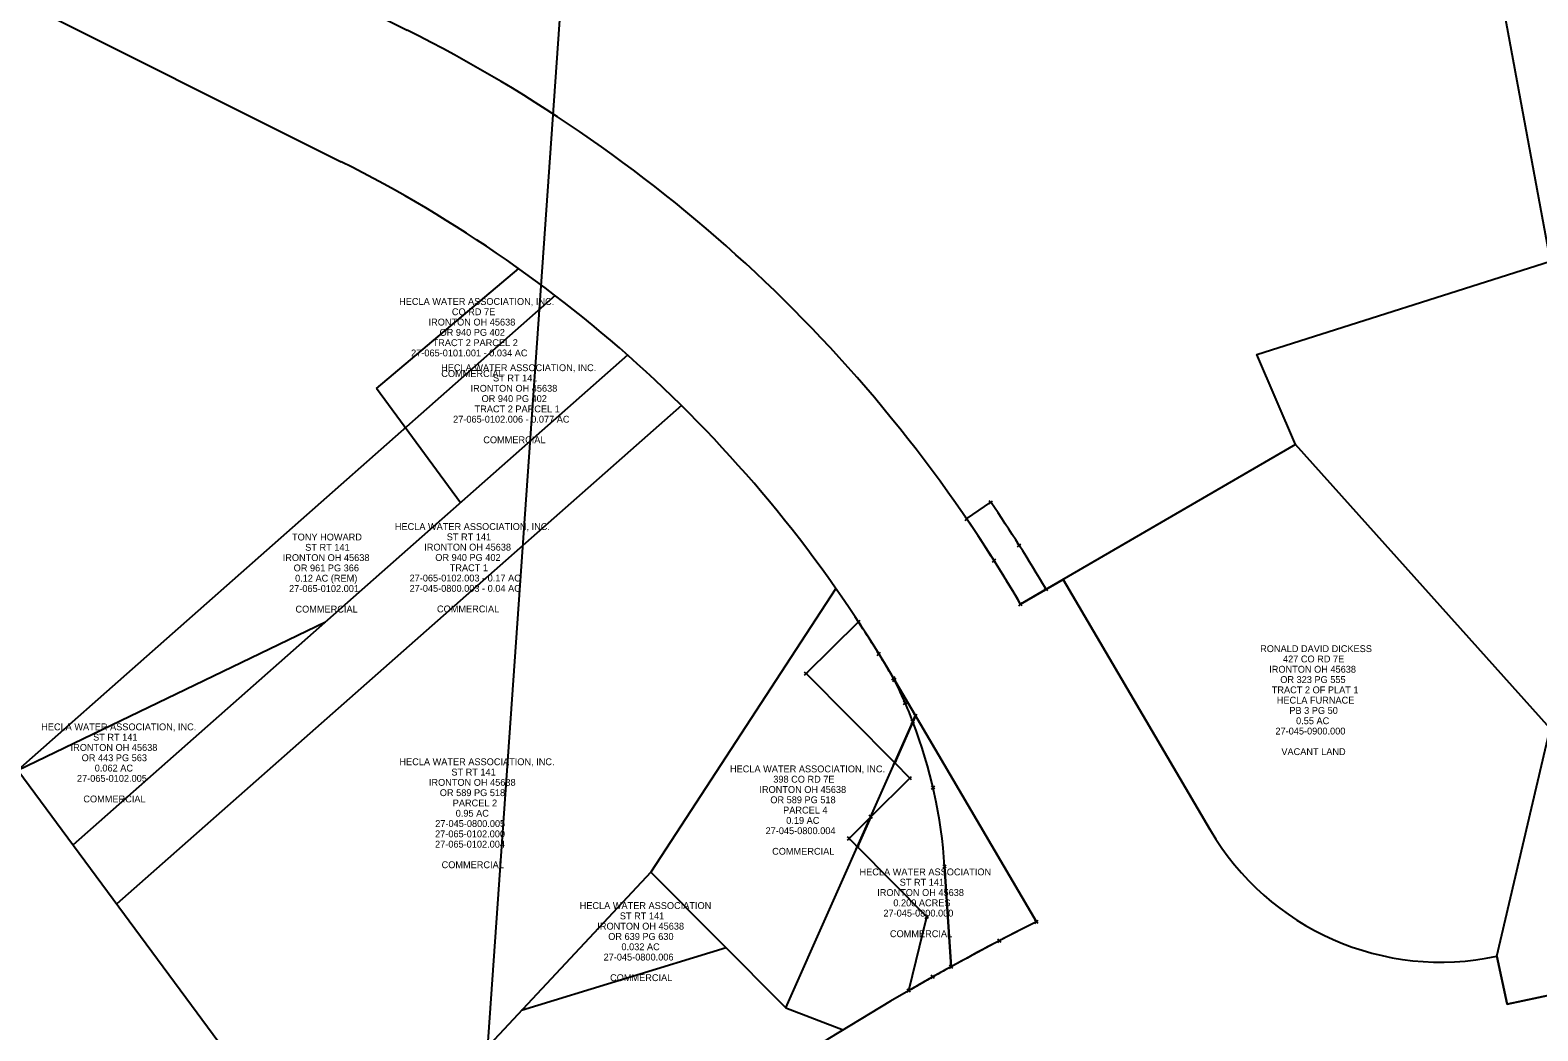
# Model space of a CAD drawing. Extents: x 1926695 to 1928303, y 198652 to 200926.
# Drawn here: x 1927197 to 1927812, y 199742 to 200150 of the extents above; entities that cross this region are included whole.
import ezdxf

# ---------------------------------------------------------------- set-up
doc = ezdxf.new("R2010")
doc.units = 0
for name, color, linetype in [('_CIVIL_CONSTRUCTION', 7, 'Continuous'), ('DR_Ditch', 7, 'Continuous'), ('DR_P_Dike', 7, 'Continuous'), ('DR_P_Storm_Sewer', 7, 'Continuous'), ('PV_P_EOP', 7, 'Continuous'), ('PV_P_Saw_Cut_Line', 7, 'Continuous'), ('RD_P_Cells', 7, 'Continuous'), ('SC_Scratch1', 7, 'Continuous')]:
    doc.layers.add(name, color=color, linetype=linetype)

msp = doc.modelspace()

# ---------------------------------------------------------------- linework, layer by layer
at = {"layer": '_CIVIL_CONSTRUCTION'}
msp.add_line((1927376.1, 199627.83), (1927467.32, 200926.12), dxfattribs=at)
at = {"layer": 'DR_Ditch'}
for p, q in [((1927589.52, 199956.71), (1927588.18, 199958.04)), ((1927588.18, 199956.71), (1927589.52, 199958.04)), ((1927579.61, 199949.95), (1927578.27, 199951.28)), ((1927578.27, 199949.95), (1927579.61, 199951.28)), ((1927601.06, 199939.16), (1927599.72, 199940.5)), ((1927599.72, 199939.16), (1927601.06, 199940.5)), ((1927590.79, 199932.95), (1927589.46, 199934.28)), ((1927589.46, 199932.95), (1927590.79, 199934.28)), ((1927611.99, 199921.24), (1927610.65, 199922.57)), ((1927610.65, 199921.24), (1927611.99, 199922.57)), ((1927601.61, 199915.21), (1927600.27, 199916.55)), ((1927600.27, 199915.21), (1927601.61, 199916.55)), ((1927535.49, 199907.99), (1927534.16, 199909.32)), ((1927534.16, 199907.99), (1927535.49, 199909.32)), ((1927543.79, 199894.93), (1927542.46, 199896.27)), ((1927542.46, 199894.93), (1927543.79, 199896.27)), ((1927514.21, 199886.85), (1927512.87, 199888.18)), ((1927512.87, 199886.85), (1927514.21, 199888.18)), ((1927549.79, 199884.97), (1927548.45, 199886.31)), ((1927548.45, 199884.97), (1927549.79, 199886.31)), ((1927550.15, 199884.36), (1927548.81, 199885.69)), ((1927548.81, 199884.36), (1927550.15, 199885.69)), ((1927554.52, 199874.97), (1927553.18, 199876.3)), ((1927553.18, 199874.97), (1927554.52, 199876.3)), ((1927558.8, 199869.61), (1927557.47, 199870.95)), ((1927557.47, 199869.61), (1927558.8, 199870.95)), ((1927557.71, 199867.15), (1927556.38, 199868.49)), ((1927556.38, 199867.15), (1927557.71, 199868.49)), ((1927550.31, 199850.49), (1927548.98, 199851.82)), ((1927548.98, 199850.49), (1927550.31, 199851.82)), ((1927556.49, 199844.27), (1927555.15, 199845.61)), ((1927555.15, 199844.27), (1927556.49, 199845.61)), ((1927565.9, 199840.42), (1927564.57, 199841.76)), ((1927564.57, 199840.42), (1927565.9, 199841.76)), ((1927540.52, 199828.42), (1927539.18, 199829.75)), ((1927539.18, 199828.42), (1927540.52, 199829.75)), ((1927531.65, 199819.61), (1927530.32, 199820.94)), ((1927530.32, 199819.61), (1927531.65, 199820.94)), ((1927535.08, 199816.16), (1927533.74, 199817.49)), ((1927533.74, 199816.16), (1927535.08, 199817.49)), ((1927570.63, 199808.26), (1927569.3, 199809.6)), ((1927569.3, 199808.26), (1927570.63, 199809.6)), ((1927563.36, 199787.68), (1927562.03, 199789.02)), ((1927562.03, 199787.68), (1927563.36, 199789.02)), ((1927608.08, 199785.69), (1927606.74, 199787.02)), ((1927606.74, 199785.69), (1927608.08, 199787.02)), ((1927592.97, 199777.93), (1927591.64, 199779.26)), ((1927591.64, 199777.93), (1927592.97, 199779.26)), ((1927573.28, 199767.34), (1927571.95, 199768.67)), ((1927571.95, 199767.34), (1927573.28, 199768.67)), ((1927556, 199757.59), (1927554.67, 199758.92)), ((1927554.67, 199757.59), (1927556, 199758.92)), ((1927565.8, 199763.17), (1927564.46, 199764.5)), ((1927564.46, 199763.17), (1927565.8, 199764.5))]:
    msp.add_line(p, q, dxfattribs=at)
at = {"layer": 'DR_P_Dike'}
for centre in [(1927588.85, 199957.38), (1927578.94, 199950.61), (1927611.32, 199921.9), (1927600.94, 199915.88)]:
    msp.add_circle(centre, 0.05, dxfattribs=at)
at = {"layer": 'DR_P_Storm_Sewer'}
for p, q in [((1926922.48, 200364.37), (1927350.83, 200149.91)), ((1927054.38, 200231.23), (1927323.97, 200096.26)), ((1927549.12, 199885.64), (1927607.41, 199786.36))]:
    msp.add_line(p, q, dxfattribs=at)
for points in [[(1927600.94, 199915.88), (1927618.24, 199925.92), (1927678.22, 199823.76)], [(1927795.13, 199772.28), (1927799.31, 199752.72), (1927856.83, 199765)]]:
    msp.add_lwpolyline(points, dxfattribs=at)
for centre, radius, start, end in [((1927080.88, 199610.74), 602.97, 30.4018, 63.404), ((1927080.89, 199610.75), 542.96, 30.41641, 63.40416), ((1927772.34, 199879.02), 109.15, 210.41641, 282.05144), ((1928078.57, 198850.88), 1047.43, 116.73228, 150.49325)]:
    msp.add_arc(centre, radius, start, end, dxfattribs=at)
at = {"layer": 'PV_P_EOP'}
for p, q in [((1927054.38, 200231.23), (1927323.97, 200096.26)), ((1927338.26, 200003.84), (1927396.33, 200052.68)), ((1927411.18, 200041.69), (1927192.02, 199848.17)), ((1927440.7, 200017.37), (1927214.57, 199817.69)), ((1927372.55, 199957.19), (1927338.26, 200003.84)), ((1927462.61, 199996.88), (1927232.4, 199793.6)), ((1927713.01, 199980.89), (1927600.94, 199915.88)), ((1927678.22, 199823.76), (1927618.24, 199925.92)), ((1927525.66, 199922.17), (1927450.16, 199806.6)), ((1927192.02, 199848.17), (1927317.58, 199908.65)), ((1927607.41, 199786.36), (1927549.12, 199885.64)), ((1927505.27, 199751.18), (1927558.14, 199870.28)), ((1927192.02, 199848.17), (1927363.59, 199616.33)), ((1927450.16, 199806.6), (1927323.3, 199670.77)), ((1927450.16, 199806.6), (1927505.27, 199751.18)), ((1927480.84, 199775.75), (1927397.43, 199750.14)), ((1927505.27, 199751.18), (1927528.62, 199742.32))]:
    msp.add_line(p, q, dxfattribs=at)
for points in [[(1927795.13, 199772.28), (1927816.89, 199865.18), (1927713.01, 199980.89), (1927697.26, 200017.66), (1927817.06, 200055.74), (1927729.84, 200526.35), (1927673.87, 200524.47), (1927316.35, 200167.17)], [(1927856.83, 199765), (1927799.31, 199752.72), (1927795.13, 199772.28)]]:
    msp.add_lwpolyline(points, dxfattribs=at)
for centre, radius, start, end in [((1927080.88, 199610.74), 602.97, 30.4018, 63.404), ((1927080.89, 199610.75), 542.96, 30.41641, 63.40416), ((1927772.34, 199879.02), 109.15, 210.41641, 282.05144), ((1928078.57, 198850.88), 1047.43, 116.73228, 150.49325)]:
    msp.add_arc(centre, radius, start, end, dxfattribs=at)
at = {"layer": 'RD_P_Cells'}
for p, q in [((1927549.48, 199885.02), (1927558.14, 199870.28)), ((1927557.05, 199867.82), (1927558.14, 199870.28)), ((1927558.14, 199870.28), (1927557.05, 199867.82)), ((1927558.14, 199870.28), (1927607.41, 199786.36)), ((1927572.62, 199768.01), (1927569.97, 199808.93))]:
    msp.add_line(p, q, dxfattribs=at)
for centre, radius, start, end in [((1927370.38, 199796.01), 200, 21.04361, 26.42961), ((1927370.38, 199796.01), 200, 3.70523, 21.04361), ((1928078.57, 198850.88), 1047.43, 116.73228, 118.88401)]:
    msp.add_arc(centre, radius, start, end, dxfattribs=at)
at = {"layer": 'SC_Scratch1'}
for p, q in [((1927578.94, 199950.61), (1927588.85, 199957.38)), ((1927611.32, 199921.9), (1927600.94, 199915.88)), ((1927513.54, 199887.51), (1927534.82, 199908.65)), ((1927549.65, 199851.15), (1927513.54, 199887.51)), ((1927549.12, 199885.64), (1927549.48, 199885.02)), ((1927557.05, 199867.82), (1927549.65, 199851.15)), ((1927549.65, 199851.15), (1927557.05, 199867.82)), ((1927555.82, 199844.94), (1927549.65, 199851.15)), ((1927539.85, 199829.08), (1927555.82, 199844.94)), ((1927530.98, 199820.28), (1927539.85, 199829.08)), ((1927539.85, 199829.08), (1927534.41, 199816.83)), ((1927534.41, 199816.83), (1927539.85, 199829.08)), ((1927534.41, 199816.83), (1927530.98, 199820.28)), ((1927562.69, 199788.35), (1927534.41, 199816.83)), ((1927569.97, 199808.93), (1927572.62, 199768.01)), ((1927555.33, 199758.26), (1927562.69, 199788.35))]:
    msp.add_line(p, q, dxfattribs=at)
for centre, radius, start, end in [((1927080.88, 199610.74), 614.97, 30.39625, 34.30934), ((1927080.88, 199610.74), 602.97, 30.4018, 34.30934), ((1927080.89, 199610.75), 542.96, 30.41641, 33.2757), ((1927370.38, 199796.01), 200, 21.04361, 26.42961), ((1927370.38, 199796.01), 200, 3.70523, 21.04361), ((1928078.57, 198850.88), 1047.43, 118.88401, 119.96943)]:
    msp.add_arc(centre, radius, start, end, dxfattribs=at)

# ---------------------------------------------------------------- texts
at = {"layer": 'PV_P_Saw_Cut_Line'}
for s, p in [('HECLA WATER ASSOCIATION, INC.', (1927347.54, 200037.87)), ('CO RD 7E', (1927369.05, 200033.67)), ('IRONTON OH 45638', (1927359.54, 200029.47)), ('TRACT 2 PARCEL 2', (1927361.19, 200021.07)), ('OR 940 PG 402', (1927364.03, 200025.27)), ('27-065-0101.001 - 0.034 AC', (1927352.42, 200016.87)), ('COMMERCIAL', (1927364.73, 200008.47)), ('HECLA WATER ASSOCIATION, INC.', (1927364.67, 200010.86)), ('IRONTON OH 45638', (1927376.66, 200002.46)), ('ST RT 141', (1927385.84, 200006.66)), ('OR 940 PG 402', (1927381.15, 199998.26)), ('27-065-0102.006 - 0.077 AC', (1927369.55, 199989.86)), ('TRACT 2 PARCEL 1', (1927378.31, 199994.06)), ('COMMERCIAL', (1927381.86, 199981.46)), ('TONY HOWARD', (1927303.88, 199941.82)), ('HECLA WATER ASSOCIATION, INC.', (1927345.79, 199946.09)), ('ST RT 141', (1927366.96, 199941.89)), ('ST RT 141', (1927309.26, 199937.62)), ('IRONTON OH 45638', (1927357.79, 199937.69)), ('IRONTON OH 45638', (1927300.08, 199933.42)), ('OR 961 PG 366', (1927304.54, 199929.22)), ('OR 940 PG 402', (1927362.28, 199933.49)), ('TRACT 1', (1927368.17, 199929.29)), ('0.12 AC (REM)', (1927305.12, 199925.02)), ('27-065-0102.003 - 0.17 AC', (1927351.79, 199925.09)), ('27-065-0102.001', (1927302.66, 199920.82)), ('27-045-0800.003 - 0.04 AC', (1927351.79, 199920.89)), ('COMMERCIAL', (1927305.28, 199912.42)), ('COMMERCIAL', (1927362.98, 199912.49)), ('RONALD DAVID DICKESS', (1927698.62, 199896.3)), ('427 CO RD 7E', (1927707.92, 199892.1)), ('IRONTON OH 45638', (1927702.31, 199887.9)), ('TRACT 2 OF PLAT 1', (1927703.35, 199879.5)), ('OR 323 PG 555', (1927706.81, 199883.7)), ('HECLA FURNACE', (1927705.4, 199875.3)), ('PB 3 PG 50', (1927710.51, 199871.1)), ('0.55 AC', (1927713.26, 199866.9)), ('HECLA WATER ASSOCIATION, INC.', (1927201.6, 199864.41)), ('ST RT 141', (1927222.77, 199860.21)), ('27-045-0900.000', (1927704.84, 199862.7)), ('IRONTON OH 45638', (1927213.6, 199856.01)), ('VACANT LAND', (1927707.26, 199854.3)), ('OR 443 PG 563', (1927218.1, 199851.81)), ('HECLA WATER ASSOCIATION, INC.', (1927347.67, 199850.18)), ('27-065-0102.005', (1927216.18, 199843.41)), ('0.062 AC', (1927223.43, 199847.61)), ('IRONTON OH 45638', (1927359.67, 199841.78)), ('ST RT 141', (1927368.84, 199845.98)), ('HECLA WATER ASSOCIATION, INC.', (1927482.44, 199847.27)), ('398 CO RD 7E', (1927500.1, 199843.07)), ('OR 589 PG 518', (1927364.13, 199837.58)), ('IRONTON OH 45638', (1927494.43, 199838.87)), ('COMMERCIAL', (1927218.79, 199835.01)), ('PARCEL 2', (1927369.4, 199833.38)), ('OR 589 PG 518', (1927498.89, 199834.67)), ('PARCEL 4', (1927504.11, 199830.47)), ('27-045-0800.005', (1927362.26, 199824.98)), ('0.95 AC', (1927370.61, 199829.18)), ('0.19 AC', (1927505.38, 199826.27)), ('27-065-0102.000', (1927362.2, 199820.78)), ('27-045-0800.004', (1927496.95, 199822.07)), ('27-065-0102.004', (1927362.19, 199816.58)), ('COMMERCIAL', (1927499.63, 199813.67)), ('COMMERCIAL', (1927364.86, 199808.18)), ('HECLA WATER ASSOCIATION', (1927535.26, 199805.26)), ('ST RT 141', (1927551.64, 199801.06)), ('IRONTON OH 45638', (1927542.47, 199796.86)), ('0.200 ACRES', (1927549.05, 199792.66)), ('HECLA WATER ASSOCIATION', (1927421.15, 199791.54)), ('ST RT 141', (1927437.53, 199787.34)), ('27-045-0800.000', (1927545, 199788.46)), ('IRONTON OH 45638', (1927428.35, 199783.14)), ('OR 639 PG 630', (1927432.8, 199778.94)), ('0.032 AC', (1927438.18, 199774.74)), ('COMMERCIAL', (1927547.66, 199780.06)), ('27-045-0800.006', (1927430.9, 199770.54)), ('COMMERCIAL', (1927433.55, 199762.14))]:
    msp.add_text(s, height=2.8, dxfattribs=at).set_placement(p)

doc.saveas('drawing.dxf')
